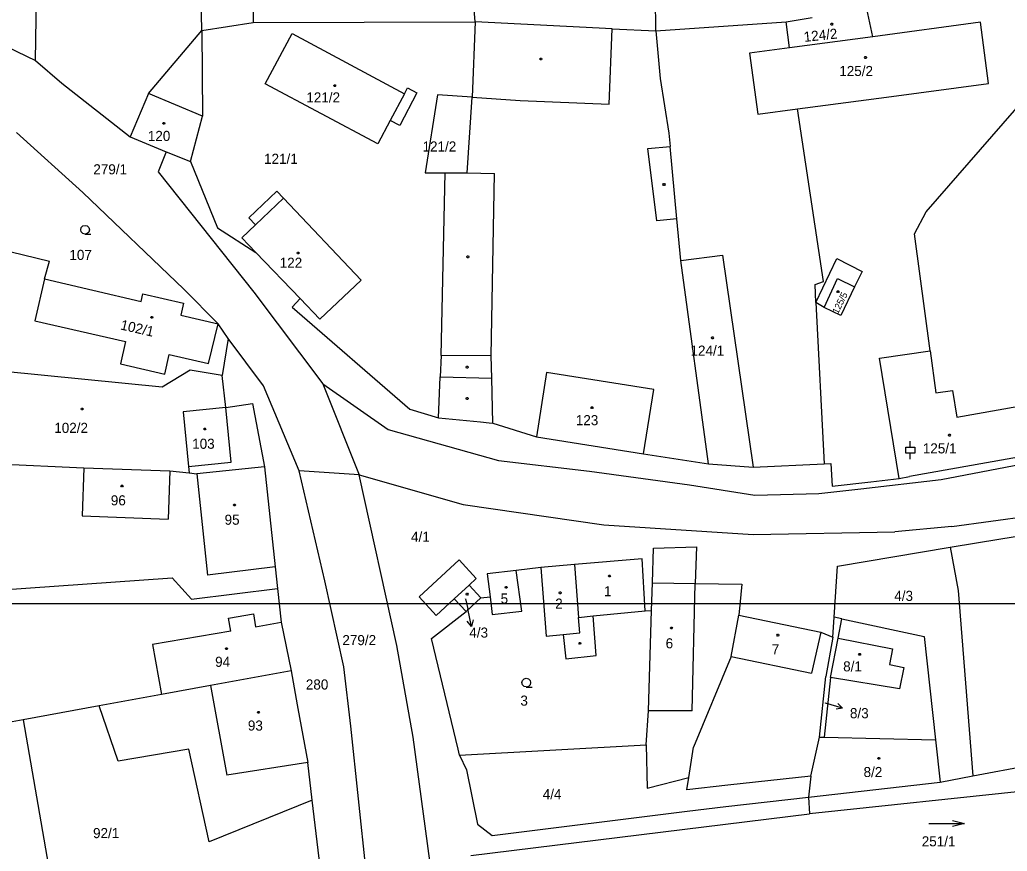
# Model space of a CAD drawing. Extents: x -812394 to -807601, y -1013097 to -1009266.
# Drawn here: x -809776.7 to -809610.1, y -1010812.8 to -1010672.5 of the extents above; entities that cross this region are included whole.
import ezdxf

# ---------------------------------------------------------------- set-up
doc = ezdxf.new("R2010")
doc.units = 0
for name, color, linetype in [('Default', 7, 'Continuous'), ('KN_HRANICE', 7, 'Continuous'), ('KN_KULTURY', 7, 'Continuous'), ('KN_PARCELY', 7, 'Continuous'), ('KN_SLUCKY', 7, 'Continuous'), ('LEGENDA', 7, 'Continuous')]:
    doc.layers.add(name, color=color, linetype=linetype)

# ---------------------------------------------------------------- blocks, each defined once
blk = doc.blocks.new('10292')
at = {"layer": 'Default'}
blk.add_line((0, 3), (0, 0), dxfattribs=at)
blk.add_lwpolyline([(-0.5, 2), (0, 3), (0.5, 2)], dxfattribs=at)
blk = doc.blocks.new('304')
at = {"layer": 'Default'}
blk.add_lwpolyline([(0, 0), (-0.38, 0.1), (-0.65, 0.37), (-0.75, 0.74), (-0.65, 1.11), (-0.38, 1.38), (-0.01, 1.48), (0.36, 1.38), (0.63, 1.11), (0.73, 0.73), (0.63, 0.35), (0.36, 0.08), (-0.02, -0.02), (0.98, -0.02)], dxfattribs=at)
blk = doc.blocks.new('NAHRADNI_SYMBOL')
at = {"layer": 'Default'}
blk.add_lwpolyline([(0.09, 0.15), (0.18, 0), (0.09, -0.15), (-0.09, -0.15), (-0.18, 0), (-0.09, 0.15), (0.09, 0.15)], dxfattribs=at)
blk = doc.blocks.new('802')
at = {"layer": 'Default'}
blk.add_line((-3, 0), (3, 0), dxfattribs=at)
blk.add_lwpolyline([(1, 0.5), (3, 0), (1, -0.5)], dxfattribs=at)
blk = doc.blocks.new('318')
at = {"layer": 'Default'}
blk.add_line((0, 2), (0, 3), dxfattribs=at)
blk.add_lwpolyline([(0, 0), (0, 1), (-0.75, 1), (-0.75, 2), (0, 2), (0.75, 2), (0.75, 1), (0, 1)], dxfattribs=at)
blk = doc.blocks.new('402')
at = {"layer": 'Default'}
blk.add_lwpolyline([(0.09, 0.15), (0.18, 0), (0.09, -0.15), (-0.09, -0.15), (-0.18, 0), (-0.09, 0.15), (0.09, 0.15)], dxfattribs=at)

msp = doc.modelspace()

# ---------------------------------------------------------------- linework, layer by layer
at = {"layer": 'KN_HRANICE'}
for p, q in [((-809669.42, -1010674.32), (-809670.02, -1010597.72)), ((-809745.99, -1010674.27), (-809746.74, -1010602.54)), ((-809738.29, -1010601.65), (-809737.29, -1010672.93)), ((-809699.85, -1010672.81), (-809703, -1010635.36)), ((-809774.04, -1010679.33), (-809773.49, -1010652.65)), ((-809632.78, -1010675.32), (-809633.83, -1010670.62)), ((-809745.99, -1010674.27), (-809737.29, -1010672.93)), ((-809737.29, -1010672.93), (-809699.85, -1010672.81)), ((-809699.85, -1010672.81), (-809700.37, -1010685.55)), ((-809676.74, -1010673.97), (-809699.85, -1010672.81)), ((-809669.42, -1010674.32), (-809647.44, -1010672.82)), ((-809647.44, -1010672.82), (-809643.04, -1010672.11)), ((-809646.86, -1010677.2), (-809647.44, -1010672.82)), ((-809614.65, -1010672.88), (-809632.78, -1010675.32)), ((-809613.27, -1010683.22), (-809614.65, -1010672.88)), ((-809784.4, -1010674.33), (-809774.04, -1010679.33)), ((-809754.98, -1010684.91), (-809745.99, -1010674.27)), ((-809745.99, -1010674.27), (-809745.83, -1010688.74)), ((-809676.74, -1010673.97), (-809669.42, -1010674.32)), ((-809669.42, -1010674.32), (-809668.69, -1010682.36)), ((-809735.29, -1010683.27), (-809730.75, -1010674.77)), ((-809730.75, -1010674.77), (-809711.79, -1010684.94)), ((-809632.78, -1010675.32), (-809646.86, -1010677.2)), ((-809646.86, -1010677.2), (-809653.59, -1010678.08)), ((-809774.04, -1010679.33), (-809769.56, -1010683.18)), ((-809653.59, -1010678.08), (-809652.21, -1010688.42)), ((-809668.69, -1010682.36), (-809667.2, -1010691.63)), ((-809769.56, -1010683.18), (-809758.03, -1010692.2)), ((-809716.29, -1010693.43), (-809735.29, -1010683.27)), ((-809711.79, -1010684.94), (-809711.27, -1010683.97)), ((-809711.27, -1010683.97), (-809709.68, -1010684.81)), ((-809630.51, -1010685.51), (-809613.27, -1010683.22)), ((-809754.98, -1010684.91), (-809758.03, -1010692.2)), ((-809709.68, -1010684.81), (-809712.59, -1010690.29)), ((-809706.24, -1010685.14), (-809708.32, -1010698.31)), ((-809700.37, -1010685.55), (-809706.24, -1010685.14)), ((-809701.22, -1010698.32), (-809700.37, -1010685.55)), ((-809645.48, -1010687.51), (-809630.51, -1010685.51)), ((-809652.21, -1010688.42), (-809645.48, -1010687.51)), ((-809641.11, -1010716.62), (-809645.48, -1010687.51)), ((-809747.86, -1010696.38), (-809745.83, -1010688.74)), ((-809714.18, -1010689.45), (-809716.29, -1010693.43)), ((-809712.59, -1010690.29), (-809714.18, -1010689.45)), ((-809777.22, -1010691.48), (-809766.01, -1010701.62)), ((-809758.03, -1010692.2), (-809751.95, -1010694.73)), ((-809667.2, -1010691.63), (-809666.99, -1010693.85)), ((-809665.84, -1010706.07), (-809666.99, -1010693.85)), ((-809751.95, -1010694.73), (-809753.31, -1010698.15)), ((-809751.95, -1010694.73), (-809747.86, -1010696.38)), ((-809747.86, -1010696.38), (-809743.3, -1010707.57)), ((-809753.31, -1010698.15), (-809737.22, -1010718.42)), ((-809708.32, -1010698.31), (-809704.94, -1010698.29)), ((-809705.58, -1010729.13), (-809704.94, -1010698.29)), ((-809704.94, -1010698.29), (-809701.22, -1010698.32)), ((-809766.01, -1010701.62), (-809749.02, -1010717.93)), ((-809738.02, -1010705.9), (-809733.32, -1010701.42)), ((-809733.32, -1010701.42), (-809732.21, -1010702.59)), ((-809732.21, -1010702.59), (-809719.07, -1010716.39)), ((-809736.91, -1010707.06), (-809738.02, -1010705.9)), ((-809665.18, -1010713.11), (-809665.84, -1010706.07)), ((-809743.3, -1010707.57), (-809736.88, -1010711.74)), ((-809739.24, -1010709.28), (-809736.91, -1010707.06)), ((-809736.88, -1010711.74), (-809739.24, -1010709.28)), ((-809781.21, -1010710.87), (-809771.66, -1010713.22)), ((-809729.37, -1010719.53), (-809736.88, -1010711.74)), ((-809642.41, -1010720.19), (-809638.87, -1010712.74)), ((-809638.87, -1010712.74), (-809634.6, -1010714.95)), ((-809772.47, -1010716.21), (-809771.66, -1010713.22)), ((-809660.52, -1010747.43), (-809665.18, -1010713.11)), ((-809772.47, -1010716.21), (-809756.21, -1010720.01)), ((-809634.6, -1010714.95), (-809635.89, -1010717.53)), ((-809749.02, -1010717.93), (-809743.23, -1010723.77)), ((-809719.07, -1010716.39), (-809726.06, -1010722.97)), ((-809642.51, -1010717.16), (-809641.11, -1010716.62)), ((-809642.41, -1010720.19), (-809642.51, -1010717.16)), ((-809635.89, -1010717.53), (-809638.17, -1010722.36)), ((-809756.21, -1010720.01), (-809755.91, -1010718.7)), ((-809755.91, -1010718.7), (-809749.04, -1010720.31)), ((-809737.22, -1010718.42), (-809725.56, -1010733.93)), ((-809729.37, -1010719.53), (-809730.7, -1010720.97)), ((-809726.06, -1010722.97), (-809729.37, -1010719.53)), ((-809749.04, -1010720.31), (-809749.51, -1010722.3)), ((-809730.7, -1010720.97), (-809710.9, -1010738.19)), ((-809642.41, -1010720.19), (-809641.01, -1010747.39)), ((-809641.03, -1010721), (-809642.41, -1010720.19)), ((-809638.17, -1010722.36), (-809641.03, -1010721)), ((-809749.51, -1010722.3), (-809743.23, -1010723.77)), ((-809741.5, -1010726.25), (-809743.23, -1010723.77)), ((-809741.5, -1010726.25), (-809742.53, -1010732.53)), ((-809735.54, -1010734.22), (-809741.5, -1010726.25)), ((-809705.58, -1010729.13), (-809705.74, -1010732.73)), ((-809623.13, -1010728.35), (-809622.2, -1010735.4)), ((-809752.63, -1010734.46), (-809779.32, -1010731.85)), ((-809747.95, -1010731.58), (-809752.63, -1010734.46)), ((-809742.53, -1010732.53), (-809747.95, -1010731.58)), ((-809741.93, -1010737.9), (-809742.53, -1010732.53)), ((-809706.04, -1010739.63), (-809705.74, -1010732.73)), ((-809729.55, -1010748.61), (-809735.54, -1010734.22)), ((-809725.56, -1010733.93), (-809719.43, -1010749.27)), ((-809725.56, -1010733.93), (-809714.56, -1010741.6)), ((-809741.93, -1010737.9), (-809749.09, -1010738.63)), ((-809741.93, -1010737.9), (-809737.44, -1010737.2)), ((-809737.44, -1010737.2), (-809735.38, -1010747.89)), ((-809618.66, -1010739.51), (-809608.17, -1010737.7)), ((-809749.09, -1010738.63), (-809748.19, -1010747.84)), ((-809710.9, -1010738.19), (-809706.04, -1010739.63)), ((-809706.04, -1010739.63), (-809698.97, -1010740.34)), ((-809698.97, -1010740.34), (-809697.48, -1010740.51)), ((-809697.48, -1010740.51), (-809696.89, -1010740.57)), ((-809696.89, -1010740.57), (-809689.54, -1010742.83)), ((-809714.56, -1010741.6), (-809695.94, -1010746.84)), ((-809689.54, -1010742.83), (-809671.5, -1010745.72)), ((-809671.5, -1010745.72), (-809660.52, -1010747.43)), ((-809606.66, -1010745.99), (-809626.64, -1010749.55)), ((-809785.91, -1010747.13), (-809765.89, -1010748.07)), ((-809748.19, -1010747.84), (-809748.08, -1010748.94)), ((-809735.38, -1010747.89), (-809746.82, -1010749.08)), ((-809735.38, -1010747.89), (-809733.57, -1010764.79)), ((-809695.94, -1010746.84), (-809680.59, -1010748.64)), ((-809660.52, -1010747.43), (-809652.99, -1010747.99)), ((-809652.99, -1010747.99), (-809641.01, -1010747.39)), ((-809641.01, -1010747.39), (-809639.91, -1010747.34)), ((-809639.91, -1010747.34), (-809639.63, -1010751.19)), ((-809621.25, -1010750.05), (-809601.6, -1010746.29)), ((-809765.89, -1010748.07), (-809766.17, -1010756.16)), ((-809765.89, -1010748.07), (-809751.37, -1010748.58)), ((-809751.37, -1010748.58), (-809751.66, -1010756.76)), ((-809751.37, -1010748.58), (-809748.08, -1010748.94)), ((-809748.08, -1010748.94), (-809746.82, -1010749.08)), ((-809719.43, -1010749.27), (-809729.55, -1010748.61)), ((-809725.23, -1010767.15), (-809729.55, -1010748.61)), ((-809713.08, -1010778.05), (-809719.43, -1010749.27)), ((-809719.43, -1010749.27), (-809701.9, -1010754.25)), ((-809680.59, -1010748.64), (-809663.74, -1010750.97)), ((-809628.36, -1010749.86), (-809626.64, -1010749.55)), ((-809663.74, -1010750.97), (-809652.69, -1010752.68)), ((-809639.63, -1010751.19), (-809633.16, -1010750.47)), ((-809634.81, -1010751.63), (-809621.25, -1010750.05)), ((-809633.16, -1010750.47), (-809628.36, -1010749.86)), ((-809652.69, -1010752.68), (-809641.93, -1010752.44)), ((-809641.93, -1010752.44), (-809634.81, -1010751.63)), ((-809701.9, -1010754.25), (-809678.17, -1010757.69)), ((-809766.17, -1010756.16), (-809751.66, -1010756.76)), ((-809619.48, -1010758), (-809604.22, -1010755.92)), ((-809678.17, -1010757.69), (-809652.96, -1010759.33)), ((-809652.96, -1010759.33), (-809629.11, -1010758.87)), ((-809619.48, -1010758), (-809629.11, -1010758.87)), ((-809611.19, -1010760.06), (-809603.15, -1010758.78)), ((-809619.76, -1010761.5), (-809611.19, -1010760.06)), ((-809669.98, -1010767.52), (-809669.8, -1010761.66)), ((-809669.8, -1010761.66), (-809662.52, -1010761.44)), ((-809662.52, -1010761.44), (-809662.78, -1010767.62)), ((-809638.74, -1010764.69), (-809619.76, -1010761.5)), ((-809619.76, -1010761.5), (-809618.42, -1010768.8)), ((-809702.57, -1010763.63), (-809709.33, -1010769.84)), ((-809699.69, -1010766.77), (-809702.57, -1010763.63)), ((-809683.14, -1010764.42), (-809688.81, -1010764.89)), ((-809671.72, -1010763.46), (-809683.14, -1010764.42)), ((-809683.14, -1010764.42), (-809682.45, -1010773.34)), ((-809671.19, -1010772.24), (-809671.72, -1010763.46)), ((-809733.57, -1010764.79), (-809733.18, -1010768.47)), ((-809692.96, -1010765.39), (-809697.85, -1010765.98)), ((-809697.85, -1010765.98), (-809697.36, -1010769.88)), ((-809688.81, -1010764.89), (-809692.96, -1010765.39)), ((-809692.01, -1010772.28), (-809692.96, -1010765.39)), ((-809688.81, -1010764.89), (-809687.88, -1010776.52)), ((-809639.3, -1010773.28), (-809638.74, -1010764.69)), ((-809794.5, -1010769.7), (-809750.96, -1010766.66)), ((-809750.96, -1010766.66), (-809747.68, -1010770.25)), ((-809722.03, -1010781.65), (-809725.23, -1010767.15)), ((-809700.87, -1010767.86), (-809699.69, -1010766.77)), ((-809698.9, -1010770), (-809700.87, -1010767.86)), ((-809670.12, -1010772.14), (-809669.98, -1010767.52)), ((-809662.78, -1010767.62), (-809654.89, -1010767.73)), ((-809654.89, -1010767.73), (-809655.37, -1010772.93)), ((-809747.68, -1010770.25), (-809733.18, -1010768.47)), ((-809733.18, -1010768.47), (-809732.57, -1010774.14)), ((-809618.42, -1010768.8), (-809615.96, -1010800.09)), ((-809709.33, -1010769.84), (-809706.45, -1010772.98)), ((-809706.45, -1010772.98), (-809703.38, -1010770.17)), ((-809703.38, -1010770.17), (-809701.41, -1010772.31)), ((-809701.41, -1010772.31), (-809698.9, -1010770)), ((-809698.9, -1010770), (-809697.36, -1010769.88)), ((-809697.36, -1010769.88), (-809696.98, -1010772.84)), ((-809707.23, -1010776.9), (-809701.41, -1010772.31)), ((-809696.98, -1010772.84), (-809692.01, -1010772.28)), ((-809679.95, -1010773.09), (-809671.19, -1010772.24)), ((-809671.19, -1010772.24), (-809670.12, -1010772.14)), ((-809670.64, -1010789.08), (-809670.12, -1010772.14)), ((-809732.57, -1010774.14), (-809730.91, -1010782.33)), ((-809682.45, -1010773.34), (-809679.95, -1010773.09)), ((-809679.45, -1010779.76), (-809679.95, -1010773.09)), ((-809656.71, -1010779.93), (-809655.37, -1010772.93)), ((-809655.37, -1010772.93), (-809641.57, -1010775.83)), ((-809639.52, -1010776.68), (-809639.3, -1010773.28)), ((-809638.02, -1010773.59), (-809639.3, -1010773.28)), ((-809638.65, -1010776.84), (-809638.02, -1010773.59)), ((-809638.02, -1010773.59), (-809624.14, -1010776.53)), ((-809641.57, -1010775.83), (-809639.52, -1010776.68)), ((-809702.75, -1010795.56), (-809707.23, -1010776.9)), ((-809687.88, -1010776.52), (-809685.04, -1010776.24)), ((-809685.04, -1010776.24), (-809684.59, -1010780.3)), ((-809639.52, -1010776.68), (-809640.74, -1010783.28)), ((-809639.93, -1010783.49), (-809638.65, -1010776.84)), ((-809624.14, -1010776.53), (-809622.24, -1010794)), ((-809710.32, -1010793.53), (-809713.08, -1010778.05)), ((-809684.59, -1010780.3), (-809679.45, -1010779.76)), ((-809656.71, -1010779.93), (-809663.05, -1010795.21)), ((-809730.91, -1010782.33), (-809744.52, -1010784.82)), ((-809730.91, -1010782.33), (-809729.89, -1010788.11)), ((-809720.85, -1010791.69), (-809722.03, -1010781.65)), ((-809641.81, -1010793.54), (-809640.74, -1010783.28)), ((-809639.93, -1010783.49), (-809640.99, -1010793.56)), ((-809744.52, -1010784.82), (-809752.77, -1010786.34)), ((-809752.77, -1010786.34), (-809763.26, -1010788.24)), ((-809763.26, -1010788.24), (-809776.12, -1010790.59)), ((-809760.07, -1010797.59), (-809763.26, -1010788.24)), ((-809729.89, -1010788.11), (-809729.78, -1010788.7)), ((-809729.78, -1010788.7), (-809728.11, -1010797.8)), ((-809671, -1010794.86), (-809670.64, -1010789.08)), ((-809776.12, -1010790.59), (-809802.82, -1010795.47)), ((-809776.12, -1010790.59), (-809768.91, -1010832.11)), ((-809718.25, -1010816.21), (-809720.85, -1010791.69)), ((-809707.49, -1010814.44), (-809710.32, -1010793.53)), ((-809643.26, -1010800.13), (-809641.81, -1010793.54)), ((-809641.81, -1010793.54), (-809640.99, -1010793.56)), ((-809640.99, -1010793.56), (-809622.24, -1010794)), ((-809622.24, -1010794), (-809621.47, -1010801.11)), ((-809748.14, -1010795.55), (-809760.07, -1010797.59)), ((-809744.75, -1010811.18), (-809748.14, -1010795.55)), ((-809702.5, -1010796.59), (-809702.75, -1010795.56)), ((-809702.5, -1010796.59), (-809671, -1010794.86)), ((-809671, -1010794.86), (-809670.86, -1010802.13)), ((-809663.83, -1010800.36), (-809663.05, -1010795.21)), ((-809615.96, -1010800.09), (-809588.54, -1010794.9)), ((-809727.35, -1010804.19), (-809728.11, -1010797.8)), ((-809702.5, -1010796.59), (-809701.33, -1010799.05)), ((-809701.33, -1010799.05), (-809699.46, -1010808.24)), ((-809670.86, -1010802.13), (-809663.83, -1010800.36)), ((-809664.14, -1010802.41), (-809663.83, -1010800.36)), ((-809643.26, -1010800.13), (-809657.25, -1010801.66)), ((-809643.26, -1010800.13), (-809643.65, -1010803.69)), ((-809643.65, -1010803.69), (-809621.47, -1010801.11)), ((-809621.47, -1010801.11), (-809615.96, -1010800.09)), ((-809657.25, -1010801.66), (-809664.14, -1010802.41)), ((-809600.38, -1010801.89), (-809643.49, -1010806.47)), ((-809727.35, -1010804.19), (-809744.75, -1010811.18)), ((-809726.02, -1010815.44), (-809727.35, -1010804.19)), ((-809657.57, -1010805.27), (-809643.65, -1010803.69)), ((-809643.65, -1010803.69), (-809643.49, -1010806.47)), ((-809696.99, -1010810.11), (-809664.09, -1010806.01)), ((-809664.09, -1010806.01), (-809657.57, -1010805.27)), ((-809700.6, -1010813.52), (-809643.49, -1010806.47)), ((-809699.46, -1010808.24), (-809696.99, -1010810.11))]:
    msp.add_line(p, q, dxfattribs=at)
for points in [[(-809623.13, -1010728.35), (-809625.78, -1010708.61), (-809623.83, -1010704.87), (-809603.55, -1010681.64)], [(-809622.2, -1010735.4), (-809619.34, -1010735.04), (-809618.66, -1010739.51)]]:
    msp.add_lwpolyline(points, dxfattribs=at)
at = {"layer": 'KN_PARCELY'}
for p, q in [((-809701.47, -1010770.18), (-809701.11, -1010771.9)), ((-809640.83, -1010787.76), (-809640.77, -1010787.78))]:
    msp.add_line(p, q, dxfattribs=at)
at = {"layer": 'KN_SLUCKY'}
for p, q in [((-809677.26, -1010686.71), (-809676.74, -1010673.97)), ((-809745.83, -1010688.74), (-809754.98, -1010684.91)), ((-809711.79, -1010684.94), (-809714.18, -1010689.45)), ((-809700.37, -1010685.55), (-809692.3, -1010686.07)), ((-809692.3, -1010686.07), (-809677.26, -1010686.71)), ((-809670.75, -1010694.2), (-809666.99, -1010693.85)), ((-809669.2, -1010706.39), (-809670.75, -1010694.2)), ((-809701.22, -1010698.32), (-809696.59, -1010698.39)), ((-809697.15, -1010729.18), (-809696.59, -1010698.39)), ((-809736.91, -1010707.06), (-809732.21, -1010702.59)), ((-809665.84, -1010706.07), (-809669.2, -1010706.39)), ((-809665.18, -1010713.11), (-809658.18, -1010712.2)), ((-809658.18, -1010712.2), (-809652.99, -1010747.99)), ((-809772.47, -1010716.21), (-809774.12, -1010723.27)), ((-809641.03, -1010721), (-809638.78, -1010716.15)), ((-809638.78, -1010716.15), (-809635.89, -1010717.53)), ((-809774.12, -1010723.27), (-809758.82, -1010726.77)), ((-809744.81, -1010730.49), (-809743.23, -1010723.77)), ((-809758.82, -1010726.77), (-809759.68, -1010730.55)), ((-809752.23, -1010732.25), (-809751.48, -1010728.96)), ((-809751.48, -1010728.96), (-809744.81, -1010730.49)), ((-809697.15, -1010729.18), (-809705.58, -1010729.13)), ((-809697.06, -1010732.94), (-809697.15, -1010729.18)), ((-809631.7, -1010729.58), (-809623.13, -1010728.35)), ((-809628.36, -1010749.86), (-809631.7, -1010729.58)), ((-809759.68, -1010730.55), (-809752.23, -1010732.25)), ((-809705.74, -1010732.73), (-809697.06, -1010732.94)), ((-809687.81, -1010731.99), (-809689.54, -1010742.83)), ((-809669.72, -1010734.88), (-809687.81, -1010731.99)), ((-809696.89, -1010740.57), (-809697.06, -1010732.94)), ((-809671.5, -1010745.72), (-809669.72, -1010734.88)), ((-809741.03, -1010747.11), (-809741.93, -1010737.9)), ((-809748.19, -1010747.84), (-809741.03, -1010747.11)), ((-809746.82, -1010749.08), (-809744.99, -1010766.19)), ((-809733.57, -1010764.79), (-809744.99, -1010766.19)), ((-809703.38, -1010770.17), (-809700.87, -1010767.86)), ((-809669.98, -1010767.52), (-809662.78, -1010767.62)), ((-809663.25, -1010789.07), (-809662.78, -1010767.62)), ((-809741.47, -1010773.44), (-809737.24, -1010772.71)), ((-809737.24, -1010772.71), (-809736.89, -1010774.91)), ((-809741.08, -1010775.63), (-809741.47, -1010773.44)), ((-809736.89, -1010774.91), (-809732.57, -1010774.14)), ((-809682.24, -1010775.95), (-809682.45, -1010773.34)), ((-809741.08, -1010775.63), (-809754.27, -1010777.89)), ((-809685.04, -1010776.24), (-809682.24, -1010775.95)), ((-809641.57, -1010775.83), (-809643.15, -1010782.76)), ((-809754.27, -1010777.89), (-809752.77, -1010786.34)), ((-809638.65, -1010776.84), (-809629.49, -1010778.64)), ((-809629.49, -1010778.64), (-809630.01, -1010781.3)), ((-809656.71, -1010779.93), (-809643.15, -1010782.76)), ((-809630.01, -1010781.3), (-809627.59, -1010781.78)), ((-809627.59, -1010781.78), (-809628.3, -1010785.39)), ((-809628.3, -1010785.39), (-809639.93, -1010783.49)), ((-809744.52, -1010784.82), (-809741.75, -1010799.98)), ((-809663.25, -1010789.07), (-809670.64, -1010789.08)), ((-809728.11, -1010797.8), (-809741.75, -1010799.98))]:
    msp.add_line(p, q, dxfattribs=at)
at = {"layer": 'LEGENDA'}
msp.add_lwpolyline([(-810040.19, -1011191.03), (-809446.19, -1011191.03), (-809446.19, -1010771.03), (-810040.19, -1010771.03)], close=True, dxfattribs=at)

# ---------------------------------------------------------------- block references
at = {"layer": 'KN_KULTURY'}
for name, p in [('NAHRADNI_SYMBOL', (-809639.73, -1010673.21)), ('402', (-809688.79, -1010679.1)), ('402', (-809634.03, -1010678.83)), ('402', (-809723.54, -1010683.59)), ('402', (-809752.37, -1010689.95)), ('402', (-809668.02, -1010700.27)), ('304', (-809765.64, -1010708.64)), ('402', (-809729.71, -1010711.84)), ('402', (-809701.1, -1010712.47)), ('402', (-809638.67, -1010718.34)), ('402', (-809754.39, -1010722.67)), ('402', (-809659.85, -1010726.15)), ('402', (-809701.21, -1010731.09)), ('402', (-809701.21, -1010736.38)), ('402', (-809680.15, -1010737.92)), ('NAHRADNI_SYMBOL', (-809766.14, -1010738.14)), ('402', (-809745.47, -1010741.52)), ('402', (-809619.88, -1010742.57)), ('318', (-809626.49, -1010746.61)), ('402', (-809759.42, -1010751.14)), ('402', (-809740.45, -1010754.37)), ('402', (-809677.22, -1010766.34)), ('402', (-809701.22, -1010769.4)), ('402', (-809694.64, -1010768.27)), ('402', (-809685.53, -1010769.19)), ('402', (-809666.77, -1010775.13)), ('402', (-809648.81, -1010776.33)), ('402', (-809682.2, -1010777.69)), ('402', (-809741.8, -1010778.62)), ('402', (-809635.03, -1010779.55)), ('304', (-809691.24, -1010785.07)), ('402', (-809736.42, -1010789.35)), ('NAHRADNI_SYMBOL', (-809631.79, -1010797.12)), ('802', (-809620.36, -1010808.13))]:
    msp.add_blockref(name, p, dxfattribs=at)
at = {"layer": 'KN_PARCELY'}
for p, rotation in [((-809701.11, -1010771.9), -168.231026), ((-809640.77, -1010787.78), -106.69535899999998)]:
    msp.add_blockref('10292', p, dxfattribs=dict(at, rotation=rotation))

# ---------------------------------------------------------------- texts
for s, height, rotation, p in [('124/2', 1.7, 5.959, (-809644.36, -1010676.21)), ('125/5', 1.14, 63.426, (-809638.7, -1010722.21)), ('102/1', 1.7, 347.27, (-809759.8, -1010724.72))]:
    msp.add_text(s, height=height, rotation=rotation, dxfattribs=at).set_placement(p)
for s, height, p in [('125/2', 1.7, (-809638.46, -1010681.96)), ('121/2', 1.7, (-809728.34, -1010686.42)), ('120', 1.7, (-809755.07, -1010692.92)), ('121/2', 1.7, (-809708.74, -1010694.7)), ('121/1', 1.7, (-809735.47, -1010696.78)), ('279/1', 1.7, (-809764.26, -1010698.55)), ('107', 1.7, (-809768.3, -1010713)), ('122', 1.7, (-809732.83, -1010714.32)), ('124/1', 1.7, (-809663.55, -1010729.15)), ('123', 1.7, (-809682.89, -1010740.89)), ('102/2', 1.7, (-809770.85, -1010742.19)), ('103', 1.7, (-809747.59, -1010744.87)), ('125/1', 1.7, (-809624.37, -1010745.65)), ('96', 1.7, (-809761.31, -1010754.42)), ('95', 1.7, (-809742.12, -1010757.69)), ('4/1', 1.7, (-809710.68, -1010760.57)), ('5', 1.7, (-809695.57, -1010770.99)), ('1', 1.7, (-809678.15, -1010769.76)), ('4/3', 1.7, (-809629.18, -1010770.54)), ('4/3', 0.1, (-809701.62, -1010770.18)), ('2', 1.7, (-809686.37, -1010771.85)), ('279/2', 1.7, (-809722.26, -1010778.01)), ('4/3', 1.7, (-809700.85, -1010776.74)), ('6', 1.7, (-809667.74, -1010778.55)), ('7', 1.7, (-809649.85, -1010779.58)), ('94', 1.7, (-809743.72, -1010781.67)), ('8/1', 1.7, (-809637.8, -1010782.44)), ('280', 1.7, (-809728.42, -1010785.5)), ('3', 1.7, (-809692.24, -1010788.22)), ('8/3', 0.1, (-809640.98, -1010787.76)), ('8/3', 1.7, (-809636.66, -1010790.34)), ('93', 1.7, (-809738.2, -1010792.43)), ('8/2', 1.7, (-809634.36, -1010800.27)), ('4/4', 1.7, (-809688.46, -1010804.01)), ('92/1', 1.7, (-809764.31, -1010810.58)), ('251/1', 1.7, (-809624.55, -1010811.97))]:
    msp.add_text(s, height=height, dxfattribs=at).set_placement(p)

doc.saveas('drawing.dxf')
